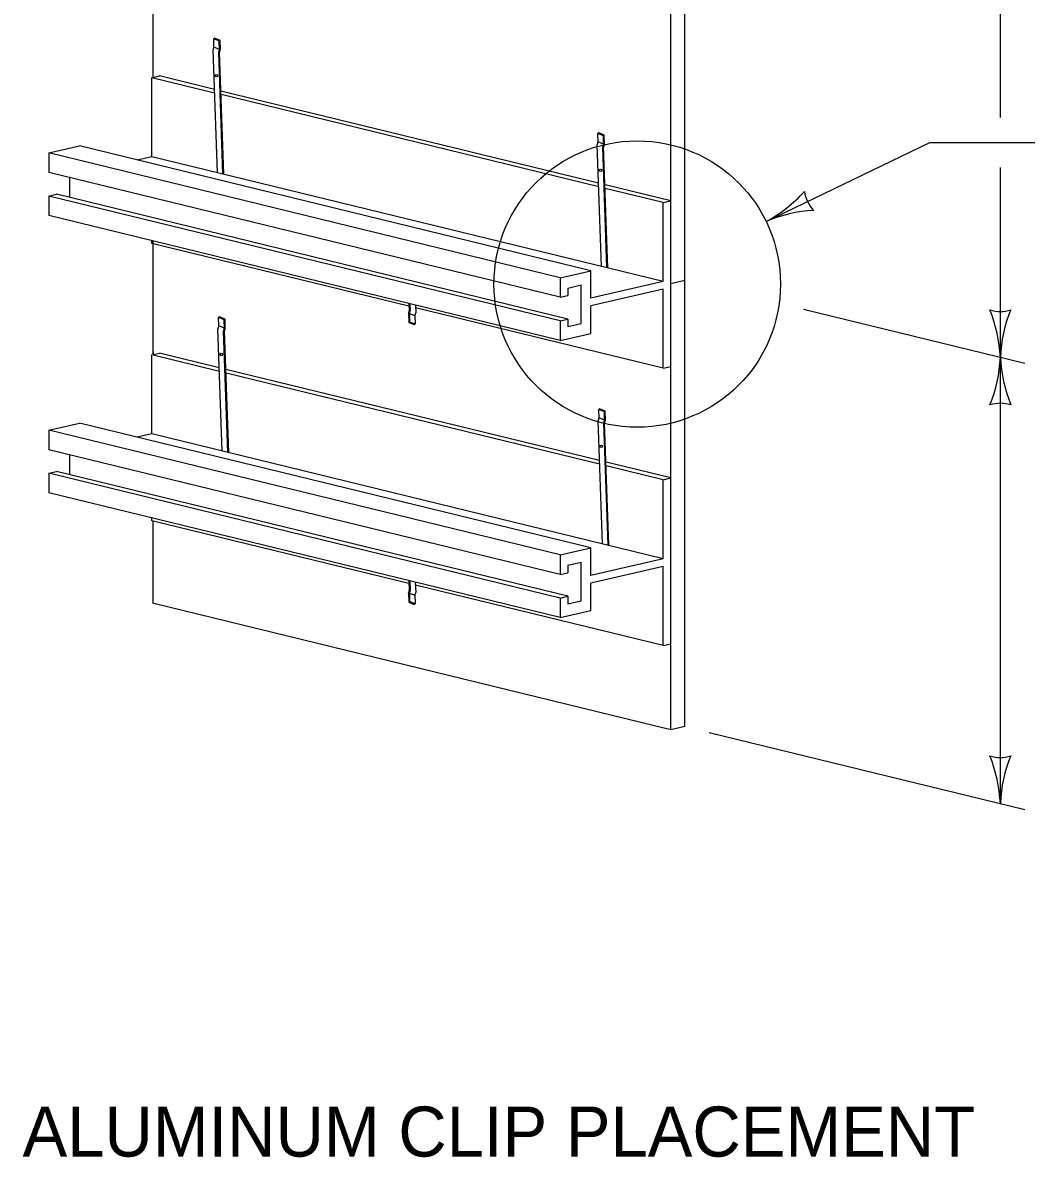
# Model space of a CAD drawing. Extents: x 49991.4 to 50021, y 49987.6 to 50011.4.
# Drawn here: x 50007.926 to 50009.529, y 49994.117 to 49995.93 of the extents above; entities that cross this region are included whole.
import ezdxf

# ---------------------------------------------------------------- set-up
doc = ezdxf.new("R2010")
doc.units = 0
for name, color, linetype in [('Level 1', 7, 'Continuous'), ('Level 2', 7, 'Continuous'), ('Level 3', 7, 'Continuous')]:
    doc.layers.add(name, color=color, linetype=linetype)

msp = doc.modelspace()

# ---------------------------------------------------------------- linework, layer by layer
at = {"layer": 'Level 1'}
for p, q in [((50008.9613, 49994.8002), (50008.9613, 49997.0091)), ((50008.9838, 49994.8053), (50008.9838, 49997.0166)), ((50008.1343, 49995.8429), (50008.1343, 49996.154)), ((50008.2325, 49995.9057), (50008.231, 49995.9046)), ((50008.2315, 49995.8912), (50008.231, 49995.9046)), ((50008.2326, 49995.904), (50008.231, 49995.9046)), ((50008.2414, 49995.902), (50008.2325, 49995.9057)), ((50008.24, 49995.901), (50008.2326, 49995.904)), ((50008.2414, 49995.902), (50008.24, 49995.901)), ((50008.2403, 49995.8877), (50008.24, 49995.901)), ((50008.2418, 49995.8878), (50008.2414, 49995.902)), ((50008.237, 49995.6906), (50008.2301, 49995.8869)), ((50008.2403, 49995.8877), (50008.2315, 49995.8912)), ((50008.2457, 49995.6885), (50008.239, 49995.8834)), ((50008.2474, 49995.6881), (50008.2404, 49995.8835)), ((50008.1322, 49995.8424), (50008.1444, 49995.8452)), ((50008.1322, 49995.7162), (50008.1322, 49995.8424)), ((50008.2325, 49995.8179), (50008.1322, 49995.8424)), ((50008.2323, 49995.8237), (50008.1444, 49995.8452)), ((50008.8459, 49995.674), (50008.2427, 49995.8212)), ((50008.8461, 49995.6682), (50008.2429, 49995.8154)), ((50008.8461, 49995.7543), (50008.8446, 49995.7532)), ((50008.8451, 49995.7398), (50008.8446, 49995.7532)), ((50008.8462, 49995.7526), (50008.8446, 49995.7532)), ((50008.855, 49995.7506), (50008.8461, 49995.7543)), ((50008.8536, 49995.7496), (50008.8462, 49995.7526)), ((50008.855, 49995.7506), (50008.8536, 49995.7496)), ((50008.8539, 49995.7363), (50008.8536, 49995.7496)), ((50008.8554, 49995.7364), (50008.855, 49995.7506)), ((50007.9677, 49995.7221), (50008.0164, 49995.7333)), ((50008.8333, 49995.5339), (50008.0164, 49995.7333)), ((50008.0241, 49995.7319), (50008.0239, 49995.7319)), ((50008.0241, 49995.7319), (50008.0239, 49995.7319)), ((50008.8505, 49995.5409), (50008.8437, 49995.7355)), ((50008.8539, 49995.7363), (50008.8451, 49995.7398)), ((50008.8593, 49995.5387), (50008.8526, 49995.732)), ((50008.8609, 49995.5383), (50008.854, 49995.7321)), ((50007.9677, 49995.7221), (50007.9677, 49995.6908)), ((50008.7846, 49995.5227), (50007.9677, 49995.7221)), ((50008.1322, 49995.7162), (50008.1089, 49995.7108)), ((50008.9491, 49995.5168), (50008.1322, 49995.7162)), ((50008.7846, 49995.4914), (50007.9677, 49995.6908)), ((50008.0012, 49995.6511), (50008.0012, 49995.6828)), ((50008.9613, 49995.6458), (50008.8562, 49995.6714)), ((50008.9491, 49995.643), (50008.8564, 49995.6656)), ((50007.9677, 49995.6533), (50007.9799, 49995.6561)), ((50007.9677, 49995.6533), (50007.9677, 49995.622)), ((50008.7846, 49995.4539), (50007.9677, 49995.6533)), ((50008.7968, 49995.4567), (50007.9799, 49995.6561)), ((50008.9491, 49995.643), (50008.9613, 49995.6458)), ((50008.9491, 49995.5168), (50008.9491, 49995.643)), ((50008.9532, 49995.644), (50008.9613, 49995.6458)), ((50008.9532, 49995.644), (50008.9613, 49995.6458)), ((50008.9532, 49995.644), (50008.9613, 49995.6458)), ((50008.9532, 49995.644), (50008.9613, 49995.6458)), ((50008.9613, 49995.6458), (50008.9613, 49995.6458)), ((50008.9613, 49995.6458), (50008.9613, 49995.6458)), ((50008.9613, 49995.5556), (50008.9613, 49995.6458)), ((50008.9613, 49995.5556), (50008.9613, 49995.6458)), ((50008.9613, 49995.6458), (50008.9613, 49995.6458)), ((50008.9613, 49995.5556), (50008.9613, 49995.6458)), ((50008.9613, 49995.6458), (50008.9613, 49995.6458)), ((50008.9613, 49995.5556), (50008.9613, 49995.6458)), ((50008.9613, 49995.6458), (50008.9613, 49995.6458)), ((50008.9613, 49995.5556), (50008.9613, 49995.6458)), ((50008.9613, 49995.4808), (50008.9613, 49995.6458)), ((50008.9613, 49995.3808), (50008.9613, 49995.6458)), ((50008.7846, 49995.4226), (50007.9677, 49995.622)), ((50008.1322, 49995.5774), (50008.1322, 49995.582)), ((50008.5429, 49995.4771), (50008.1322, 49995.5774)), ((50008.1343, 49995.4011), (50008.1343, 49995.5813)), ((50008.7846, 49995.5227), (50008.8333, 49995.5339)), ((50008.8333, 49995.4901), (50008.8333, 49995.5339)), ((50008.7846, 49995.5227), (50008.7846, 49995.4914)), ((50008.9491, 49995.5168), (50008.8333, 49995.4901)), ((50008.9838, 49995.5184), (50008.9613, 49995.5132)), ((50008.7846, 49995.4914), (50008.7968, 49995.4942)), ((50008.7968, 49995.5062), (50008.8181, 49995.5111)), ((50008.7968, 49995.5062), (50008.7968, 49995.4942)), ((50008.8181, 49995.4496), (50008.8181, 49995.5111)), ((50008.9491, 49995.5043), (50008.8333, 49995.4776)), ((50008.9491, 49995.378), (50008.9491, 49995.5043)), ((50008.5429, 49995.4811), (50008.5434, 49995.4698)), ((50008.5445, 49995.4805), (50008.5449, 49995.4699)), ((50008.5533, 49995.4786), (50008.5538, 49995.4664)), ((50008.8333, 49995.4338), (50008.8333, 49995.4776)), ((50008.2403, 49995.4601), (50008.2388, 49995.459)), ((50008.2393, 49995.4456), (50008.2388, 49995.459)), ((50008.2404, 49995.4584), (50008.2388, 49995.459)), ((50008.2492, 49995.4564), (50008.2403, 49995.4601)), ((50008.2478, 49995.4554), (50008.2404, 49995.4584)), ((50008.5421, 49995.4655), (50008.5425, 49995.4514)), ((50008.5436, 49995.4657), (50008.5524, 49995.4621)), ((50008.5436, 49995.4657), (50008.544, 49995.4524)), ((50008.5524, 49995.4621), (50008.5529, 49995.4488)), ((50008.9491, 49995.378), (50008.5536, 49995.4745)), ((50008.2445, 49995.2456), (50008.2379, 49995.4413)), ((50008.2481, 49995.4421), (50008.2393, 49995.4456)), ((50008.2481, 49995.4421), (50008.2477, 49995.4554)), ((50008.2492, 49995.4564), (50008.2478, 49995.4554)), ((50008.2496, 49995.4422), (50008.2492, 49995.4564)), ((50008.5425, 49995.4514), (50008.5439, 49995.4524)), ((50008.5425, 49995.4514), (50008.5514, 49995.4477)), ((50008.5439, 49995.4524), (50008.5513, 49995.4494)), ((50008.5513, 49995.4494), (50008.5528, 49995.4489)), ((50008.5514, 49995.4477), (50008.5529, 49995.4488)), ((50008.7846, 49995.4539), (50008.7968, 49995.4567)), ((50008.7846, 49995.4539), (50008.7846, 49995.4226)), ((50008.7968, 49995.4567), (50008.7968, 49995.4447)), ((50008.7968, 49995.4447), (50008.8181, 49995.4496)), ((50008.2535, 49995.2434), (50008.2467, 49995.4378)), ((50008.2552, 49995.243), (50008.2482, 49995.4379)), ((50008.7846, 49995.4226), (50008.8333, 49995.4338)), ((50008.1343, 49995.4047), (50008.1343, 49995.4011)), ((50008.1322, 49995.3992), (50008.1444, 49995.402)), ((50008.1322, 49995.273), (50008.1322, 49995.3992)), ((50008.2402, 49995.3728), (50008.1322, 49995.3992)), ((50008.24, 49995.3787), (50008.1444, 49995.402)), ((50008.8474, 49995.2304), (50008.2504, 49995.3761)), ((50008.8476, 49995.2246), (50008.2507, 49995.3703)), ((50008.9491, 49995.378), (50008.9613, 49995.3808)), ((50008.8476, 49995.3131), (50008.8461, 49995.312)), ((50008.8565, 49995.3094), (50008.8476, 49995.3131)), ((50008.852, 49995.0973), (50008.8452, 49995.2943)), ((50008.8466, 49995.2986), (50008.8461, 49995.312)), ((50008.8477, 49995.3114), (50008.8461, 49995.312)), ((50008.8554, 49995.2951), (50008.8466, 49995.2986)), ((50008.8551, 49995.3084), (50008.8477, 49995.3114)), ((50008.8565, 49995.3094), (50008.8551, 49995.3084)), ((50008.8554, 49995.2951), (50008.8551, 49995.3084)), ((50008.8569, 49995.2952), (50008.8565, 49995.3094)), ((50007.9677, 49995.2789), (50008.0164, 49995.2901)), ((50007.9677, 49995.2789), (50007.9677, 49995.2476)), ((50008.7846, 49995.0795), (50007.9677, 49995.2789)), ((50008.8333, 49995.0907), (50008.0164, 49995.2901)), ((50008.0241, 49995.2887), (50008.0239, 49995.2887)), ((50008.861, 49995.0951), (50008.8541, 49995.2908)), ((50008.8625, 49995.0947), (50008.8555, 49995.2909)), ((50008.1322, 49995.273), (50008.1089, 49995.2676)), ((50008.9491, 49995.0736), (50008.1322, 49995.273)), ((50008.7846, 49995.0482), (50007.9677, 49995.2476)), ((50008.0012, 49995.2079), (50008.0012, 49995.2396)), ((50008.9613, 49995.2026), (50008.8578, 49995.2279)), ((50008.9491, 49995.1998), (50008.858, 49995.2221)), ((50007.9677, 49995.2101), (50007.9799, 49995.2129)), ((50007.9677, 49995.2101), (50007.9677, 49995.1788)), ((50008.7846, 49995.0107), (50007.9677, 49995.2101)), ((50008.7968, 49995.0135), (50007.9799, 49995.2129)), ((50008.9491, 49995.1998), (50008.9613, 49995.2026)), ((50008.9491, 49995.0736), (50008.9491, 49995.1998)), ((50008.9532, 49995.2008), (50008.9613, 49995.2026)), ((50008.9532, 49995.2008), (50008.9613, 49995.2026)), ((50008.9613, 49995.1124), (50008.9613, 49995.2026)), ((50008.9613, 49995.2026), (50008.9613, 49995.2026)), ((50008.9613, 49995.1124), (50008.9613, 49995.2026)), ((50008.9613, 49995.2026), (50008.9613, 49995.2026)), ((50008.9613, 49995.1124), (50008.9613, 49995.2026)), ((50008.9613, 49995.2026), (50008.9613, 49995.2026)), ((50008.9613, 49995.1124), (50008.9613, 49995.2026)), ((50008.9613, 49995.0376), (50008.9613, 49995.2026)), ((50008.9613, 49994.9376), (50008.9613, 49995.2026)), ((50008.7846, 49994.9794), (50007.9677, 49995.1788)), ((50008.1322, 49995.1342), (50008.1322, 49995.1388)), ((50008.5429, 49995.034), (50008.1322, 49995.1342)), ((50008.1343, 49995.0018), (50008.1343, 49995.1337)), ((50008.7846, 49995.0795), (50008.8333, 49995.0907)), ((50008.7846, 49995.0795), (50008.7846, 49995.0482)), ((50008.8333, 49995.0469), (50008.8333, 49995.0907)), ((50008.7968, 49995.063), (50008.8181, 49995.0679)), ((50008.7968, 49995.063), (50008.7968, 49995.051)), ((50008.8181, 49995.0064), (50008.8181, 49995.0679)), ((50008.9491, 49995.0736), (50008.8333, 49995.0469)), ((50008.9491, 49995.0611), (50008.8333, 49995.0344)), ((50008.9491, 49994.9348), (50008.9491, 49995.0611)), ((50008.7846, 49995.0482), (50008.7968, 49995.051)), ((50008.5427, 49995.0384), (50008.5435, 49995.0228)), ((50008.5444, 49995.038), (50008.5449, 49995.0229)), ((50008.5531, 49995.0359), (50008.5538, 49995.0194)), ((50008.9491, 49994.9348), (50008.5533, 49995.0314)), ((50008.8333, 49994.9906), (50008.8333, 49995.0344)), ((50008.5421, 49995.0185), (50008.5425, 49995.0043)), ((50008.5425, 49995.0043), (50008.5439, 49995.0053)), ((50008.5425, 49995.0043), (50008.5514, 49995.0006)), ((50008.5436, 49995.0186), (50008.5524, 49995.0151)), ((50008.5436, 49995.0186), (50008.5439, 49995.0053)), ((50008.5439, 49995.0053), (50008.5513, 49995.0023)), ((50008.5524, 49995.0151), (50008.5529, 49995.0017)), ((50008.7846, 49995.0107), (50008.7968, 49995.0135)), ((50008.7846, 49995.0107), (50008.7846, 49994.9794)), ((50008.7968, 49995.0135), (50008.7968, 49995.0015)), ((50008.7968, 49995.0015), (50008.8181, 49995.0064)), ((50008.9613, 49994.8002), (50008.1353, 49995.0018)), ((50008.5513, 49995.0023), (50008.5529, 49995.0017)), ((50008.5514, 49995.0006), (50008.5529, 49995.0017)), ((50008.7846, 49994.9794), (50008.8333, 49994.9906)), ((50008.9491, 49994.9348), (50008.9613, 49994.9376)), ((50008.9838, 49994.8053), (50008.9613, 49994.8002))]:
    msp.add_line(p, q, dxfattribs=at)
for centre in [(50008.2353, 49995.8456), (50008.8489, 49995.6942), (50008.2431, 49995.4), (50008.8504, 49995.253)]:
    msp.add_circle(centre, 0.00193, dxfattribs=at)
for centre, major_axis, start_param, end_param in [((50008.231, 49995.8868), (0.0005, 0.00437), 6.236921, 7.853982), ((50008.2398, 49995.8833), (0.0005, 0.00437), 6.257502, 7.853982), ((50008.2413, 49995.8834), (0.0005, 0.00437), 6.22181, 7.853982), ((50008.8446, 49995.7354), (0.0005, 0.00437), 6.236921, 7.853982), ((50008.8534, 49995.7319), (0.0005, 0.00437), 6.257502, 7.853982), ((50008.8549, 49995.732), (0.0005, 0.00437), 6.22181, 7.853982), ((50008.5426, 49995.47), (-0.0005, -0.00437), 0, 1.570796), ((50008.5441, 49995.4701), (-0.0005, -0.00437), 0, 1.570796), ((50008.5529, 49995.4666), (-0.0005, -0.00437), 0, 1.570796), ((50008.2388, 49995.4412), (0.0005, 0.00437), 6.236921, 7.853982), ((50008.2476, 49995.4377), (0.0005, 0.00437), 6.257502, 7.853982), ((50008.2491, 49995.4378), (0.0005, 0.00437), 6.22181, 7.853982), ((50008.8461, 49995.2942), (0.0005, 0.00437), 6.236921, 7.853982), ((50008.8549, 49995.2907), (0.0005, 0.00437), 6.257502, 7.853982), ((50008.8564, 49995.2908), (0.0005, 0.00437), 6.22181, 7.853982), ((50008.5426, 49995.0229), (-0.0005, -0.00437), 6.22181, 7.853982), ((50008.5441, 49995.023), (-0.0005, -0.00437), 6.257859, 7.853982), ((50008.5529, 49995.0195), (-0.0005, -0.00437), 6.236921, 7.853982)]:
    msp.add_ellipse(centre, major_axis=major_axis, ratio=0.190283, start_param=start_param, end_param=end_param, dxfattribs=at)
at = {"layer": 'Level 3'}
for p, q in [((50009.4877, 49995.779), (50009.4877, 49996.8933)), ((50009.1136, 49995.6124), (50009.3749, 49995.739)), ((50009.3749, 49995.739), (50009.7555, 49995.739)), ((50009.4877, 49995.3954), (50009.4877, 49995.699)), ((50009.1732, 49995.4722), (50009.5266, 49995.3859)), ((50009.4877, 49994.6823), (50009.4877, 49995.3954)), ((50009.0227, 49994.7958), (50009.5266, 49994.6728))]:
    msp.add_line(p, q, dxfattribs=at)
msp.add_circle((50008.9076, 49995.5126), 0.2289, dxfattribs=at)
for centre, radius, start, end in [((50009.0017, 49995.8168), 0.233, 298.6955, 317.9454), ((50009.2289, 49995.6683), 0.0548, 188.007, 223.7294), ((50009.2022, 49995.4085), 0.2223, 93.3242, 113.5077), ((50009.4877, 49995.5236), 0.0548, 252.1388, 287.8612), ((50009.255, 49995.3839), 0.233, 2.8273, 22.0772), ((50009.7098, 49995.3863), 0.2223, 157.456, 177.6395), ((50009.2656, 49995.4046), 0.2223, 337.456, 357.6395), ((50009.7204, 49995.4069), 0.233, 182.8273, 202.0772), ((50009.4877, 49995.2672), 0.0548, 72.1388, 107.8612), ((50009.4877, 49994.8105), 0.0548, 252.1388, 287.8612), ((50009.255, 49994.6708), 0.233, 2.8273, 22.0772), ((50009.7098, 49994.6731), 0.2223, 157.456, 177.6395)]:
    msp.add_arc(centre, radius, start, end, dxfattribs=at)

# ---------------------------------------------------------------- texts
at = {"layer": 'Level 2'}
msp.add_text('ALUMINUM CLIP PLACEMENT', height=0.08, dxfattribs=at).set_placement((50007.9257, 49994.1178))

doc.saveas('drawing.dxf')
